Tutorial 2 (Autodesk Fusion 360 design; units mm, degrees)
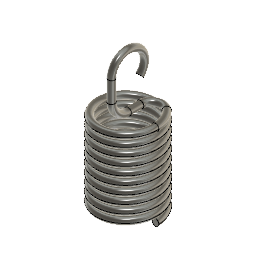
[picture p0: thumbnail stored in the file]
coil_primitive "CoilPrimitive1" Diameter 40 SectionSize 5 TaperAngle 0 Revolutions 10 Height 60
work_plane "WorkPlane2" AlongDistance 60
sketch "Sketch3" plane through (0, 0, 60) normal (0, 0, 1) x axis (1, 0, 0)
  line L1 (17.5, 0) -> (22.5, 0)
  line L2 (0, 8.9443) -> (0, 0)
  arc A1 centre (0, 0) radius 20 clockwise from (13.3333, 14.9071) to (20, 0)
  arc A2 centre (8, 8.9443) radius 8 clockwise from (0, 8.9443) to (13.3333, 14.9071)
  point P1 (0, 0)
  point P2 (0, 0)
  point P9 (0, 0)
  point P3 (20, 0)
  coincident P1 P2
  coincident P2 P9
  vertical L2
  tangent A1 A2
  tangent A2 L2
  coincident P3 L1
  dimension "d8" radius A1 = 20
  dimension "d10" radius A2 = 8
sweep "Sweep1" TwistAngle 0 TaperAngle 0
sketch "Sketch4" plane through (0, 0, 0) normal (1, 0, 0) x axis (0, 1, 0)
  line L1 (-12, 87) -> (-12, 72)
  line L2 (20.4742, 87) -> (0, 87)
  line L3 (8.4853, 78.5147) -> (0, 87)
  arc A1 centre (0, 72) radius 12 clockwise from (0, 60) to (-12, 72)
  arc A2 centre (0, 87) radius 12 clockwise from (-12, 87) to (8.4853, 78.5147)
  point P2 (0, 60)
  point P5 (0, 60)
  point P8 (0, 87)
  point P9 (0, 87)
  point P11 (0, 87)
  point P3 (-12, 72)
  point P6 (-12, 87)
  coincident P2 P5
  vertical L1
  tangent A1 L1
  tangent L1 A2
  coincident P8 P9
  horizontal L2
  vertical P2 P8
  coincident P8 P11
  dimension "d18" radius A1 = 12
  dimension "d19" distance P3 P6 = 15
  dimension "d20" radius A2 = 12
  dimension "d21" angle L2 L3 = 45
sweep "Sweep2" TwistAngle 0 TaperAngle 0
